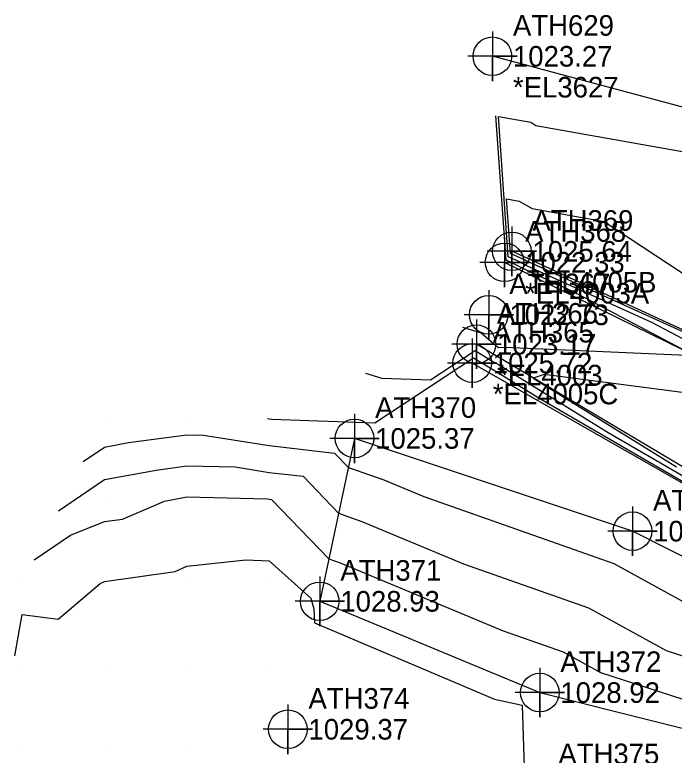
# Model space of a CAD drawing. Extents: x 1213164 to 1213550, y 766120 to 766870.
# Drawn here: x 1213169.1 to 1213249.2, y 766449.1 to 766539 of the extents above; entities that cross this region are included whole.
import ezdxf

# ---------------------------------------------------------------- set-up
doc = ezdxf.new("R2010")
doc.units = 0
for name, color, linetype in [('Default', 7, 'Continuous'), ('Exist DTM Breakline', 7, 'Continuous'), ('Exist DTM Breakline Cogo Comment', 7, 'Continuous'), ('Exist DTM Breakline Cogo Elevation', 7, 'Continuous'), ('Exist DTM Breakline Cogo Number', 7, 'Continuous'), ('Exist DTM Breakline Cogo Point CELL', 7, 'Continuous'), ('Exist DTM Drainline Cogo Comment', 7, 'Continuous'), ('Exist DTM Drainline Cogo Elevation', 7, 'Continuous'), ('Exist DTM Drainline Cogo Number', 7, 'Continuous'), ('Exist DTM Drainline Cogo Point CELL', 7, 'Continuous'), ('Exist DTM QL2 LIDAR Elevation Point', 7, 'Continuous'), ('Exist DTM Regular Point CELL', 7, 'Continuous'), ('Exist DTM Regular Point Cogo Elevation', 7, 'Continuous'), ('Exist DTM Regular Point Cogo Number', 7, 'Continuous'), ('Exist DTM Regular Point Underwater CELL', 7, 'Continuous'), ('Exist DTM Regular Point Underwater Cogo Elevation', 7, 'Continuous'), ('Exist DTM Regular Point Underwater Cogo Number', 7, 'Continuous'), ('Exist Environmental Wetland Boundary Cogo Comment', 7, 'Continuous'), ('Exist Environmental Wetland Boundary Cogo Elevation', 7, 'Continuous'), ('Exist Environmental Wetland Boundary Cogo Number', 7, 'Continuous'), ('Exist Environmental Wetland Boundary Cogo Point CELL', 7, 'Continuous'), ('Exist Hydro Stream or Body of Water', 7, 'Continuous')]:
    doc.layers.add(name, color=color, linetype=linetype)

msp = doc.modelspace()

# ---------------------------------------------------------------- linework, layer by layer
at = {"layer": 'Default'}
for points in [[(1213223.4522835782, 766501.0990636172), (1213225.7273167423, 766500.417861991), (1213227.7784803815, 766498.6388193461), (1213228.6049630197, 766498.694247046), (1213251.6057317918, 766497.6713433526), (1213236.8667792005, 766505.4526248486), (1213231.2971667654, 766507.9754647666), (1213229.1962276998, 766509.0414330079), (1213228.7504468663, 766509.2435858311), (1213227.5175, 766526.7724230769)], [(1213302.237526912, 766492.2400042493), (1213291.8869665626, 766494.1944431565), (1213280.3513956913, 766496.7988423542), (1213269.1433913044, 766496.1008197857), (1213258.4343595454, 766495.3541406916), (1213246.4477447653, 766501.6823531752), (1213231.430104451, 766508.4848197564), (1213230.1335065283, 766509.1426837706), (1213229.0183851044, 766509.6483693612), (1213227.82, 766526.6858411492), (1213231.7452264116, 766525.9756047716), (1213232.384419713, 766525.6060891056), (1213255.3908439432, 766521.5189148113), (1213260.9941407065, 766517.8376878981), (1213268.0661230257, 766515.1395785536), (1213276.8144201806, 766515.9927831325), (1213284.2753601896, 766516.1182322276), (1213289.4289636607, 766512.4142018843), (1213289.74796495, 766512.1484445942), (1213306.4730306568, 766498.23270073), (1213311.3375821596, 766496.8069984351), (1213311.4064809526, 766491.6109761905), (1213312.8713956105, 766490.6043669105), (1213302.237526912, 766492.2400042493)], [(1213231.070785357, 766509.2439345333), (1213229.2863233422, 766510.0531528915), (1213228.8199999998, 766516.6828838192), (1213230.3474094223, 766516.4065120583), (1213231.9253504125, 766515.4943092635), (1213240.6597993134, 766513.9426028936), (1213259.385570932, 766501.6402356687), (1213270.7925038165, 766497.2882519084), (1213258.7948522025, 766496.451724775), (1213256.0287103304, 766497.912081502), (1213231.5630421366, 766508.9941747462), (1213231.070785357, 766509.2439345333)], [(1213211.663662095, 766495.519962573), (1213213.6826010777, 766494.9154419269), (1213219.5577649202, 766494.7141357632), (1213224.9816556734, 766498.2876721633), (1213226.958693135, 766497.062518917), (1213227.826995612, 766496.5558650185), (1213241.159022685, 766488.3053824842), (1213253.5675473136, 766481.1159566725)], [(1213199.7832754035, 766490), (1213199.9999999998, 766489.9656022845), (1213200.2912607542, 766489.9323356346), (1213212.8156236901, 766489.5032018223), (1213224.7822053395, 766497.3873973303), (1213225.608464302, 766496.875371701), (1213227.4372783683, 766495.8082599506), (1213232.8561839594, 766492.4547874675), (1213253.311741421, 766480.6029584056)], [(1213257.5716084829, 766492.1833588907), (1213233.3693369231, 766495.35514), (1213232.0588285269, 766494.9257890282), (1213249.4618614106, 766484.155977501)], [(1213177.3903593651, 766484.7807187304), (1213179.9999999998, 766486.5391297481), (1213182.9156410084, 766487.0843589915), (1213190, 766488.032966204), (1213192.0115718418, 766487.9884281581), (1213199.9999999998, 766486.7205347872), (1213207.9226277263, 766485.8156436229), (1213209.5953588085, 766484.0732829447), (1213213.919644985, 766482.5557335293), (1213218.7809312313, 766480.5337518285), (1213241.8495821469, 766472.4040495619), (1213256.20619088, 766464.510006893)], [(1213174.413016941, 766478.8260338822), (1213179.9999999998, 766482.5906183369), (1213186.2420996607, 766483.7579003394), (1213190, 766484.2610893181), (1213195.868852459, 766484.1311475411), (1213199.9999999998, 766483.4754672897), (1213204.0971194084, 766483.007510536), (1213208.408227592, 766478.5169468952), (1213211.254125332, 766477.5182177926), (1213223.6000709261, 766472.3831002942), (1213238.7657924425, 766467.0384964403), (1213248.2040699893, 766461.848819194), (1213262.2482288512, 766457.3021442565)], [(1213171.435674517, 766472.871349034), (1213175.8370657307, 766475.8370657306), (1213179.9999999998, 766477.4959953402), (1213182.1879373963, 766477.8120626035), (1213187.261402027, 766480), (1213189.5685583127, 766480.4314416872), (1213190, 766480.4892124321), (1213199.726133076, 766480.273866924), (1213199.9999999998, 766480.2303997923), (1213200.2716110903, 766480.1993774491), (1213207.2210963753, 766472.9606108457), (1213208.5886056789, 766472.4807020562), (1213228.4192106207, 766464.23244876), (1213235.6820027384, 766461.6729433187), (1213240.2019490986, 766459.1876314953), (1213261.825254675, 766452.1872733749)], [(1213169.0884030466, 766461.2208687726), (1213170, 766466.2138052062), (1213174.3374099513, 766465.6625900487), (1213179.4609903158, 766470), (1213179.9999999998, 766470.2147953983), (1213188.5500699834, 766471.4499300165), (1213190, 766472.0752139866), (1213197.1412160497, 766472.8587839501), (1213199.9999999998, 766472.7274150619), (1213205.0383873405, 766468.2069825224), (1213205.4026470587, 766466.900882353), (1213205.4678081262, 766465.190751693), (1213227.328634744, 766455.9379532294), (1213230.7239666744, 766455.1990821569), (1213231.0326136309, 766445.1780503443), (1213232.021415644, 766444.8682285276), (1213243.076208, 766439.375128), (1213255.6098, 766434.52024)]]:
    msp.add_lwpolyline(points, dxfattribs=at)
at = {"layer": 'Exist DTM Breakline'}
for points in [[(1213319.115, 766489.2660000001), (1213302.33, 766492.8640000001), (1213279.67, 766497.667), (1213258.903, 766496.781), (1213229.457, 766510.311)], [(1213296.571, 766471.333), (1213272.272, 766473.348), (1213253.224, 766480.427), (1213224.639, 766496.741)], [(1213263.0320000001, 766466.78), (1213244.11, 766476.337), (1213210.348, 766487.596), (1213206.1230000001, 766467.821), (1213232.848, 766456.742), (1213261.607, 766449.5480000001), (1213263.0320000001, 766466.78)]]:
    msp.add_lwpolyline(points, dxfattribs=at)
at = {"layer": 'Exist DTM Breakline Cogo Point CELL'}
for points in [[(1213229.457, 766513.311), (1213229.457, 766507.311), (1213229.457, 766510.311), (1213232.457, 766510.311), (1213226.457, 766510.311)], [(1213224.639, 766499.741), (1213224.639, 766493.741), (1213224.639, 766496.741), (1213227.639, 766496.741), (1213221.639, 766496.741)], [(1213210.348, 766490.596), (1213210.348, 766484.596), (1213210.348, 766487.596), (1213213.348, 766487.596), (1213207.348, 766487.596)], [(1213244.11, 766479.337), (1213244.11, 766473.337), (1213244.11, 766476.337), (1213247.11, 766476.337), (1213241.11, 766476.337)], [(1213206.1230000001, 766470.821), (1213206.1230000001, 766464.821), (1213206.1230000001, 766467.821), (1213209.1230000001, 766467.821), (1213203.1230000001, 766467.821)], [(1213232.848, 766459.742), (1213232.848, 766453.742), (1213232.848, 766456.742), (1213235.848, 766456.742), (1213229.848, 766456.742)]]:
    msp.add_lwpolyline(points, dxfattribs=at)
for centre in [(1213229.457, 766510.311), (1213224.639, 766496.741), (1213210.348, 766487.596), (1213244.11, 766476.337), (1213206.1230000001, 766467.821), (1213232.848, 766456.742)]:
    msp.add_circle(centre, 2.344041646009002, dxfattribs=at)
at = {"layer": 'Exist DTM Drainline Cogo Point CELL'}
for points in [[(1213228.572, 766511.974), (1213228.572, 766505.974), (1213228.572, 766508.974), (1213231.572, 766508.974), (1213225.572, 766508.974)], [(1213225.147, 766502.034), (1213225.147, 766496.034), (1213225.147, 766499.034), (1213228.147, 766499.034), (1213222.147, 766499.034)]]:
    msp.add_lwpolyline(points, dxfattribs=at)
for centre in [(1213228.572, 766508.974), (1213225.147, 766499.034)]:
    msp.add_circle(centre, 2.344041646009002, dxfattribs=at)
at = {"layer": 'Exist DTM QL2 LIDAR Elevation Point'}
for p, q in [((1213180, 766490), (1213180, 766490)), ((1213190, 766490), (1213190, 766490)), ((1213200, 766490), (1213200, 766490)), ((1213180, 766480), (1213180, 766480)), ((1213190, 766480), (1213190, 766480)), ((1213200, 766480), (1213200, 766480)), ((1213170, 766470), (1213170, 766470)), ((1213180, 766470), (1213180, 766470)), ((1213190, 766470), (1213190, 766470)), ((1213200, 766470), (1213200, 766470)), ((1213170, 766460), (1213170, 766460)), ((1213180, 766460), (1213180, 766460)), ((1213190, 766460), (1213190, 766460)), ((1213200, 766460), (1213200, 766460)), ((1213170, 766450), (1213170, 766450)), ((1213180, 766450), (1213180, 766450)), ((1213190, 766450), (1213190, 766450))]:
    msp.add_line(p, q, dxfattribs=at)
at = {"layer": 'Exist DTM Regular Point CELL'}
msp.add_lwpolyline([(1213202.253, 766455.285), (1213202.253, 766449.285), (1213202.253, 766452.285), (1213205.253, 766452.285), (1213199.253, 766452.285)], dxfattribs=at)
msp.add_circle((1213202.253, 766452.285), 2.344041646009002, dxfattribs=at)
at = {"layer": 'Exist DTM Regular Point Underwater CELL'}
msp.add_lwpolyline([(1213226.647, 766505.611), (1213226.647, 766499.611), (1213226.647, 766502.611), (1213229.647, 766502.611), (1213223.647, 766502.611)], dxfattribs=at)
msp.add_circle((1213226.647, 766502.611), 2.344041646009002, dxfattribs=at)
at = {"layer": 'Exist Environmental Wetland Boundary Cogo Point CELL'}
msp.add_lwpolyline([(1213227.09, 766536.988), (1213227.09, 766530.988), (1213227.09, 766533.988), (1213230.09, 766533.988), (1213224.09, 766533.988)], dxfattribs=at)
msp.add_circle((1213227.09, 766533.988), 2.344041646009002, dxfattribs=at)
at = {"layer": 'Exist Hydro Stream or Body of Water'}
for points in [[(1213309.3190000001, 766492.246), (1213285.214, 766511.13), (1213261.681, 766524.7540000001), (1213227.09, 766533.988)], [(1213319.329, 766487.569), (1213302.0960000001, 766491.285), (1213281.341, 766495.5380000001), (1213258.142, 766494.464), (1213228.572, 766508.974)], [(1213298.396, 766478.0650000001), (1213273.101, 766474.9), (1213253.962, 766481.907), (1213225.147, 766499.034)]]:
    msp.add_lwpolyline(points, dxfattribs=at)

# ---------------------------------------------------------------- texts
at = {"layer": 'Exist DTM Breakline Cogo Comment'}
for s, p in [('*EL4005B', (1213231.957, 766505.311)), ('*EL4005C', (1213227.139, 766491.741))]:
    msp.add_text(s, height=2.5, dxfattribs=at).set_placement(p)
at = {"layer": 'Exist DTM Breakline Cogo Elevation'}
for s, p in [('1025.64', (1213231.957, 766509.061)), ('1025.72', (1213227.139, 766495.491)), ('1025.37', (1213212.848, 766486.346)), ('1025.27', (1213246.61, 766475.087)), ('1028.93', (1213208.6230000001, 766466.571)), ('1028.92', (1213235.348, 766455.492))]:
    msp.add_text(s, height=2.5, dxfattribs=at).set_placement(p)
at = {"layer": 'Exist DTM Breakline Cogo Number'}
for s, p in [('ATH369', (1213231.957, 766512.811)), ('ATH365', (1213227.139, 766499.241)), ('ATH370', (1213212.848, 766490.096)), ('ATH357', (1213246.61, 766478.837)), ('ATH371', (1213208.6230000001, 766470.321)), ('ATH372', (1213235.348, 766459.242))]:
    msp.add_text(s, height=2.5, dxfattribs=at).set_placement(p)
at = {"layer": 'Exist DTM Drainline Cogo Comment'}
for s, p in [('*EL4003A', (1213231.072, 766503.974)), ('*EL4003', (1213227.647, 766494.034))]:
    msp.add_text(s, height=2.5, dxfattribs=at).set_placement(p)
at = {"layer": 'Exist DTM Drainline Cogo Elevation'}
for s, p in [('1022.33', (1213231.072, 766507.724)), ('1023.17', (1213227.647, 766497.784))]:
    msp.add_text(s, height=2.5, dxfattribs=at).set_placement(p)
at = {"layer": 'Exist DTM Drainline Cogo Number'}
for s, p in [('ATH368', (1213231.072, 766511.474)), ('ATH366', (1213227.647, 766501.534))]:
    msp.add_text(s, height=2.5, dxfattribs=at).set_placement(p)
at = {"layer": 'Exist DTM Regular Point Cogo Elevation'}
msp.add_text('1029.37', height=2.5, dxfattribs=at).set_placement((1213204.753, 766451.035))
at = {"layer": 'Exist DTM Regular Point Cogo Number'}
for s, p in [('ATH374', (1213204.753, 766454.785)), ('ATH375', (1213235.1030000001, 766448.047))]:
    msp.add_text(s, height=2.5, dxfattribs=at).set_placement(p)
at = {"layer": 'Exist DTM Regular Point Underwater Cogo Elevation'}
msp.add_text('1022.73', height=2.5, dxfattribs=at).set_placement((1213229.147, 766501.361))
at = {"layer": 'Exist DTM Regular Point Underwater Cogo Number'}
msp.add_text('ATH367', height=2.5, dxfattribs=at).set_placement((1213229.147, 766505.111))
at = {"layer": 'Exist Environmental Wetland Boundary Cogo Comment'}
msp.add_text('*EL3627', height=2.5, dxfattribs=at).set_placement((1213229.59, 766528.988))
at = {"layer": 'Exist Environmental Wetland Boundary Cogo Elevation'}
msp.add_text('1023.27', height=2.5, dxfattribs=at).set_placement((1213229.59, 766532.738))
at = {"layer": 'Exist Environmental Wetland Boundary Cogo Number'}
msp.add_text('ATH629', height=2.5, dxfattribs=at).set_placement((1213229.59, 766536.488))

doc.saveas('drawing.dxf')
